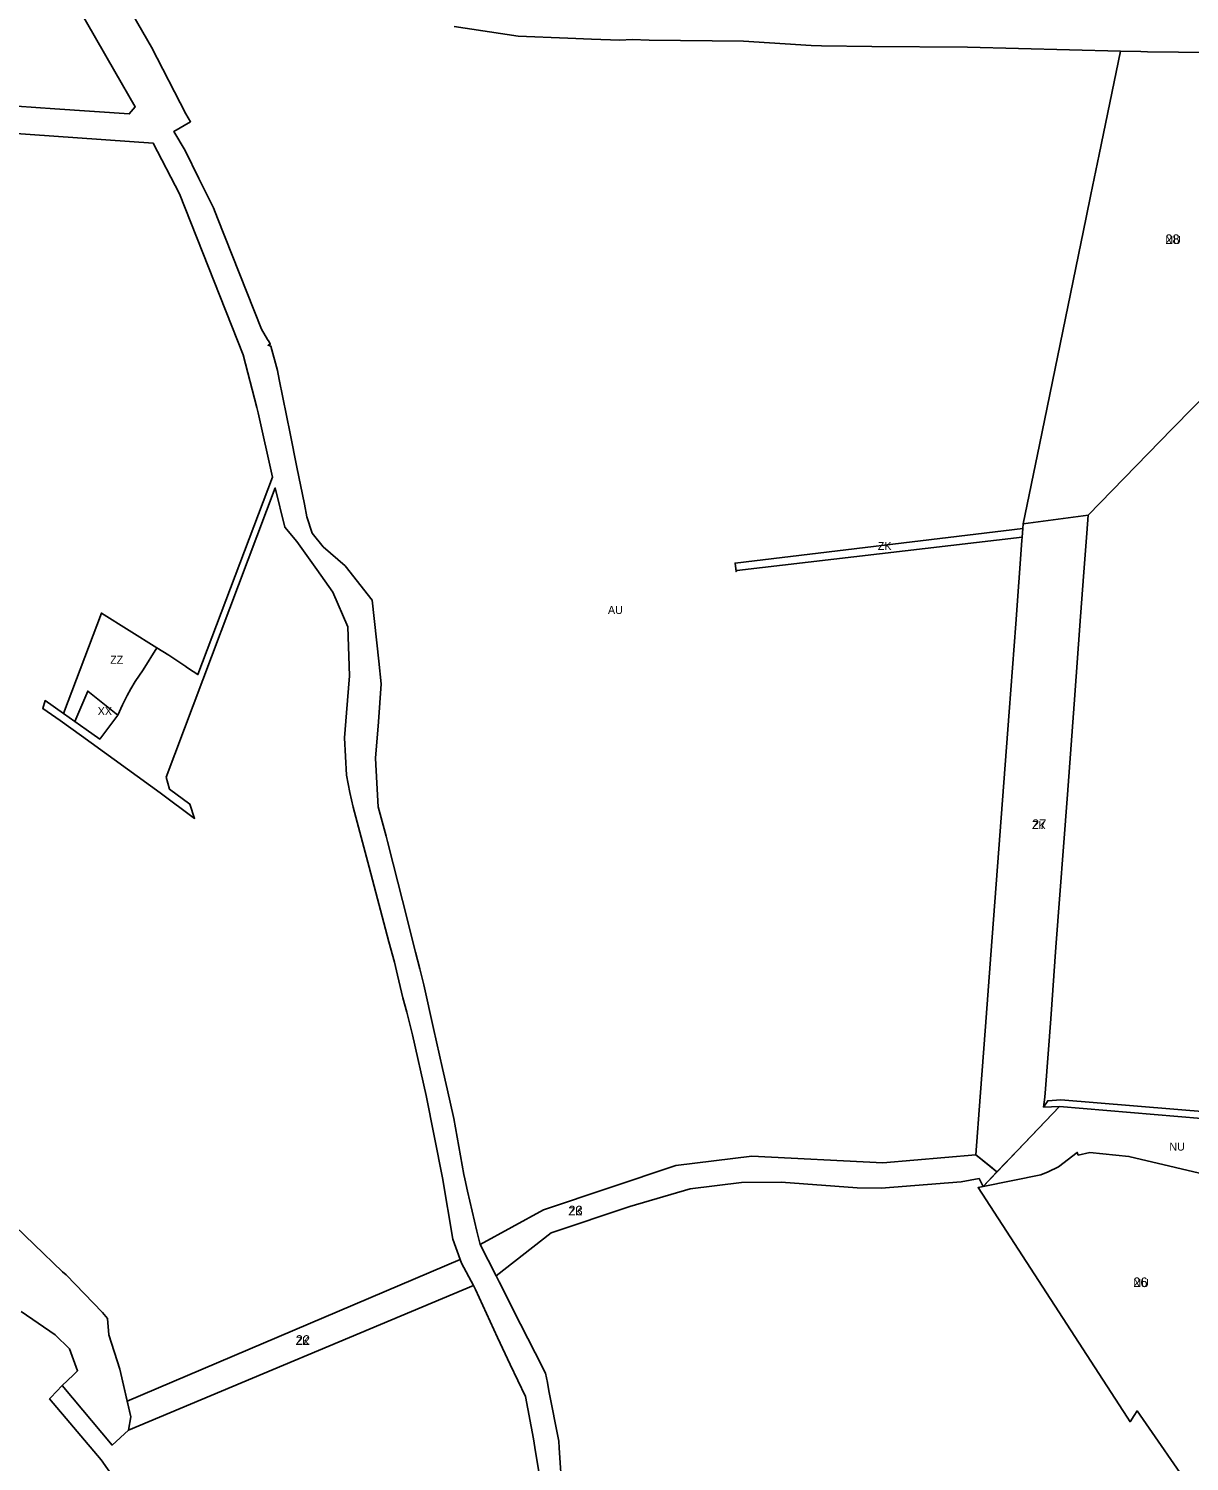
# Model space of a CAD drawing. Extents: x -541351 to -537540, y -1162694 to -1159725.
# Drawn here: x -539459 to -538734, y -1162211 to -1161316 of the extents above; entities that cross this region are included whole.
import ezdxf

# ---------------------------------------------------------------- set-up
doc = ezdxf.new("R2010")
doc.units = 0
for name, color, linetype in [('90550013', 7, 'Continuous'), ('90670013', 7, 'Continuous'), ('90710013', 7, 'Continuous'), ('90710023', 7, 'Continuous'), ('90730013', 7, 'Continuous'), ('90730023', 7, 'Continuous'), ('90750013', 7, 'Continuous'), ('ID_navrh', 7, 'Continuous')]:
    doc.layers.add(name, color=color, linetype=linetype)

msp = doc.modelspace()

# ---------------------------------------------------------------- linework, layer by layer
at = {"layer": '90550013'}
msp.add_lwpolyline([(-539403.27, -1161745.18), (-539414.57, -1161760.24), (-539423.02, -1161754.26), (-539430.1, -1161749.19), (-539422.09, -1161730.19)], close=True, dxfattribs=at)
at = {"layer": '90670013'}
msp.add_lwpolyline([(-539378.9, -1161703.23), (-539387.58, -1161716.88), (-539392.51, -1161724.29), (-539395.12, -1161728.84), (-539397.57, -1161733.03), (-539400.32, -1161738.89), (-539403.27, -1161745.18), (-539422.09, -1161730.19), (-539430.1, -1161749.19), (-539437.27, -1161744.18), (-539413.6, -1161681.54)], close=True, dxfattribs=at)
at = {"layer": '90710013'}
msp.add_lwpolyline([(-539017.23, -1161655.55), (-539017.95, -1161650.26), (-538838.219, -1161628.655), (-538838.622, -1161634.028), (-539016.74, -1161654.92)], close=True, dxfattribs=at)
at = {"layer": '90710023'}
for points in [[(-538838.219, -1161628.655), (-538838.005, -1161625.799), (-538797.48, -1161620.29), (-538798.31, -1161631.51), (-538800.12, -1161655.85), (-538802.17, -1161683.57), (-538806.25, -1161738.46), (-538810.43, -1161794.77), (-538817.52, -1161890.24), (-538820.83, -1161934.92), (-538824.09, -1161978.8), (-538824.47, -1161983.94), (-538825.25, -1161990.14), (-538815.36, -1161989.8), (-538842.019, -1162017.71), (-538854.36, -1162030.631), (-538867.535, -1162019.889), (-538864.817, -1161983.614), (-538861.529, -1161939.738), (-538858.176, -1161894.991), (-538846.804, -1161743.228), (-538842.689, -1161688.306), (-538838.789, -1161636.259), (-538838.622, -1161634.028)], [(-538854.36, -1162030.631), (-538863.08, -1162039.76), (-538865.57, -1162034.76), (-538865.57, -1162034.76), (-538876.72, -1162036.74), (-538926.62, -1162040.85), (-538941.77, -1162040.48), (-538989.17, -1162037.11), (-539013.92, -1162037.13), (-539045.95, -1162041.27), (-539083.65, -1162052.18), (-539132.72, -1162068.62), (-539167.17, -1162095.62), (-539177.1, -1162076.06), (-539137.485, -1162054.397), (-539054.974, -1162026.594), (-539007.532, -1162020.741), (-538925.739, -1162024.857), (-538867.535, -1162019.889), (-538858.418, -1162027.322)], [(-539188.8, -1162087.6), (-539181.321, -1162101.563), (-539396.737, -1162192.032), (-539395.121, -1162183.629), (-539397.38, -1162173.819), (-539189.627, -1162085.25)]]:
    msp.add_lwpolyline(points, close=True, dxfattribs=at)
at = {"layer": '90730013'}
msp.add_lwpolyline([(-538636.08, -1162004.76), (-538644.52, -1162009.98), (-538647.92, -1162012.08), (-538664.06, -1162033.48), (-538673.38, -1162035.73), (-538671.98, -1162042.69), (-538672.267, -1162044.823), (-538672.267, -1162044.823), (-538713.86, -1162034.77), (-538772.02, -1162020.88), (-538796.41, -1162018.51), (-538803.58, -1162020.1), (-538804.26, -1162018.41), (-538816.04, -1162027.52), (-538822.45, -1162030.47), (-538826.9, -1162032.51), (-538863.08, -1162039.76), (-538815.36, -1161989.8), (-538711.96, -1161998.43)], close=True, dxfattribs=at)
msp.add_lwpolyline([(-539473.3, -1162058.96), (-539437.95, -1162093.1), (-539435.62, -1162095.01), (-539412.98, -1162118.53), (-539409.81, -1162122.16), (-539409.81, -1162122.16), (-539408.87, -1162132.42), (-539408.87, -1162132.42), (-539401.987, -1162153.807), (-539395.121, -1162183.629), (-539396.737, -1162192.032), (-539406.94, -1162201.22), (-539438.02, -1162164.06), (-539431.19, -1162157.52), (-539428.42, -1162154.88), (-539433.54, -1162141.24), (-539442.45, -1162132.43), (-539463.62, -1162117.77)], dxfattribs=at)
at = {"layer": '90730023'}
for points in [[(-538838.005, -1161625.799), (-538827.847, -1161576.385), (-538798.665, -1161434.423), (-538795.685, -1161419.928), (-538790.55, -1161394.945), (-538777.276, -1161330.371), (-538764.566, -1161330.69), (-538760.434, -1161330.846), (-538702.278, -1161331.538), (-538660.482, -1161332.245), (-538705.32, -1161525.94), (-538744.9, -1161566.45), (-538797.48, -1161620.29)], [(-538713.86, -1162034.77), (-538672.267, -1162044.823), (-538673.105, -1162051.048), (-538695.05, -1162214.09), (-538712.27, -1162226.46), (-538729.02, -1162231.4), (-538730.919, -1162231.96), (-538766.94, -1162179.94), (-538768.78, -1162182.83), (-538771.26, -1162186.72), (-538773.11, -1162183.87), (-538866.22, -1162040.39), (-538863.08, -1162039.76), (-538826.9, -1162032.51), (-538822.45, -1162030.47), (-538816.04, -1162027.52), (-538804.26, -1162018.41), (-538803.58, -1162020.1), (-538796.41, -1162018.51), (-538772.02, -1162020.88)]]:
    msp.add_lwpolyline(points, close=True, dxfattribs=at)
at = {"layer": '90750013'}
for points in [[(-539468.39, -1161234.85), (-539453.999, -1161259.118), (-539447.73, -1161269.69), (-539434.98, -1161291.19), (-539405.14, -1161343.09), (-539392.4, -1161365.24), (-539396.15, -1161369.7), (-539442.69, -1161366.45), (-539490.23, -1161363.16)], [(-539193.318, -1161315.105), (-539153.268, -1161321.094), (-539122.293, -1161322.252), (-539107.636, -1161322.955), (-539089.891, -1161323.5), (-539082.223, -1161323.25), (-539071.627, -1161323.569), (-539012.669, -1161324.213), (-538970.356, -1161326.967), (-538963.886, -1161327.088), (-538932.513, -1161327.519), (-538872.877, -1161327.968), (-538777.276, -1161330.371), (-538777.276, -1161330.371), (-538790.55, -1161394.945), (-538795.685, -1161419.928), (-538798.665, -1161434.423), (-538827.847, -1161576.385), (-538838.005, -1161625.799), (-538838.219, -1161628.655), (-539017.95, -1161650.26), (-539017.23, -1161655.55), (-539016.74, -1161654.92), (-538838.622, -1161634.028), (-538838.789, -1161636.259), (-538842.689, -1161688.306), (-538846.804, -1161743.228), (-538858.176, -1161894.991), (-538861.529, -1161939.738), (-538864.817, -1161983.614), (-538867.535, -1162019.889), (-538925.739, -1162024.857), (-539007.532, -1162020.741), (-539054.974, -1162026.594), (-539137.485, -1162054.397), (-539177.1, -1162076.06), (-539177.1, -1162076.06), (-539179.07, -1162067.59), (-539184.9, -1162042.56), (-539186.67, -1162034.94), (-539187.18, -1162032.19), (-539193.59, -1161997.34), (-539197.76, -1161978.7), (-539200.6, -1161966.02), (-539206.22, -1161940.94), (-539212.32, -1161913.69), (-539214.84, -1161903.7), (-539217.45, -1161893.33), (-539225.57, -1161861.14), (-539231.34, -1161838.25), (-539234.86, -1161824.29), (-539235.74, -1161820.78), (-539240.72, -1161802.49), (-539241.52, -1161787.71), (-539242.37, -1161772.11), (-539240.64, -1161749.54), (-539238.81, -1161725.75), (-539240.34, -1161711.55), (-539244.42, -1161673.52), (-539261.46, -1161651.91), (-539275.02, -1161640.13), (-539281.97, -1161631.64), (-539285.25, -1161621.38), (-539286.85, -1161613.44), (-539291.53, -1161590.26), (-539295.77, -1161569.23), (-539302.55, -1161535.61), (-539303.69, -1161529.93), (-539307.78, -1161514.67), (-539309.47, -1161514.21), (-539308.09, -1161513.51), (-539308.92, -1161512.11), (-539309.76, -1161510.68), (-539313.61, -1161504.16), (-539341.16, -1161434.73), (-539343.67, -1161428.41), (-539352.75, -1161410.03), (-539361.37, -1161392.57), (-539368.278, -1161380.57), (-539357.878, -1161374.583), (-539360.762, -1161369.573), (-539382.245, -1161327.916), (-539417.292, -1161267.224)], [(-539505.512, -1161379.19), (-539381.181, -1161387.997), (-539381.181, -1161387.997), (-539364.89, -1161419.69), (-539325.02, -1161520.27), (-539316.47, -1161553.16), (-539315.76, -1161556.43), (-539306.78, -1161596.54), (-539353.29, -1161719.96), (-539359.12, -1161716.15), (-539360.62, -1161715.05), (-539360.91, -1161714.86), (-539371.51, -1161707.71), (-539378.9, -1161703.23), (-539413.6, -1161681.54), (-539437.27, -1161744.18), (-539448.59, -1161736.16), (-539450.22, -1161741.11), (-539439.41, -1161748.71), (-539426, -1161758.14), (-539376.97, -1161793.72), (-539355.34, -1161809.82), (-539358.35, -1161800.84), (-539371.01, -1161791.56), (-539373.09, -1161783.93), (-539305.07, -1161603.34), (-539299.04, -1161627.81), (-539291.45, -1161636.72), (-539279.15, -1161654.33), (-539269.09, -1161668.45), (-539259.73, -1161690.18), (-539258.67, -1161720.64), (-539260.49, -1161743.77), (-539261.83, -1161759.51), (-539260.63, -1161782.68), (-539258.35, -1161793.49), (-539256.35, -1161802.83), (-539246.32, -1161840.14), (-539234.16, -1161886.78), (-539230.64, -1161899.55), (-539228.65, -1161907.73), (-539225.42, -1161921.81), (-539222.91, -1161930.72), (-539219.35, -1161944.98), (-539210.77, -1161982.93), (-539200.52, -1162034.32), (-539194.04, -1162072.72), (-539189.627, -1162085.25), (-539189.627, -1162085.25), (-539397.38, -1162173.819), (-539401.987, -1162153.807), (-539408.87, -1162132.42), (-539408.87, -1162132.42), (-539409.81, -1162122.16), (-539409.81, -1162122.16), (-539412.98, -1162118.53), (-539435.62, -1162095.01), (-539437.95, -1162093.1), (-539473.3, -1162058.96)], [(-538650.79, -1161999.07), (-538814.6, -1161985.57), (-538822.66, -1161986.2), (-538825.25, -1161990.14), (-538824.47, -1161983.94), (-538824.09, -1161978.8), (-538820.83, -1161934.92), (-538817.52, -1161890.24), (-538810.43, -1161794.77), (-538806.25, -1161738.46), (-538802.17, -1161683.57), (-538800.12, -1161655.85), (-538798.31, -1161631.51), (-538797.48, -1161620.29), (-538744.9, -1161566.45), (-538705.32, -1161525.94)], [(-539125.86, -1162230.82), (-539127.7, -1162203.08), (-539127.98, -1162198.77), (-539134.14, -1162167.31), (-539135.1, -1162162.18), (-539136.3, -1162156.43), (-539142.82, -1162143.59), (-539151.92, -1162125.67), (-539165.27, -1162099.36), (-539167.17, -1162095.62), (-539132.72, -1162068.62), (-539083.65, -1162052.18), (-539045.95, -1162041.27), (-539013.92, -1162037.13), (-538989.17, -1162037.11), (-538941.77, -1162040.48), (-538926.62, -1162040.85), (-538876.72, -1162036.74), (-538865.57, -1162034.76), (-538863.08, -1162039.76), (-538866.22, -1162040.39), (-538773.11, -1162183.87), (-538771.26, -1162186.72), (-538768.78, -1162182.83), (-538766.94, -1162179.94), (-538730.919, -1162231.96)], [(-539363.42, -1162282.15), (-539413.74, -1162210.51), (-539445.96, -1162172.37), (-539445.09, -1162171.46), (-539441.51, -1162167.71), (-539438.02, -1162164.06), (-539406.94, -1162201.22), (-539396.737, -1162192.032), (-539181.321, -1162101.563), (-539180.01, -1162104.01), (-539166.2, -1162134.06), (-539158.34, -1162150.83), (-539148.72, -1162171), (-539143.8, -1162197.43), (-539142.44, -1162205.39), (-539139.57, -1162222.82)]]:
    msp.add_lwpolyline(points, dxfattribs=at)

# ---------------------------------------------------------------- texts
at = {"layer": '90550013'}
msp.add_text('XX', height=5, rotation=360, dxfattribs=at).set_placement((-539415.86, -1161745.215))
at = {"layer": '90670013'}
msp.add_text('ZZ', height=5, rotation=360, dxfattribs=at).set_placement((-539408.085, -1161713.166))
at = {"layer": '90710013'}
msp.add_text('ZK', height=5, rotation=0, dxfattribs=at).set_placement((-538928.775, -1161642.103))
at = {"layer": '90710023'}
msp.add_text('ZK', height=5, dxfattribs=at).set_placement((-538832.508, -1161816.402))
for rotation, p in [(360, (-539121.957, -1162057.754)), (0, (-539292.236, -1162138.641))]:
    msp.add_text('ZK', height=5, rotation=rotation, dxfattribs=at).set_placement(p)
at = {"layer": '90730013'}
msp.add_text('NU', height=5, rotation=360, dxfattribs=at).set_placement((-538746.752, -1162017.311))
at = {"layer": '90730023'}
for p in [(-538749.243, -1161450.938), (-538769.243, -1162102.55)]:
    msp.add_text('NU', height=5, rotation=0, dxfattribs=at).set_placement(p)
at = {"layer": '90750013'}
msp.add_text('AU', height=5, rotation=0, dxfattribs=at).set_placement((-539097.284, -1161682.062))
at = {"layer": 'ID_navrh'}
for s, rotation, p in [('28', 360, (-538749.243, -1161450.938)), ('27', 0, (-538832.508, -1161816.402)), ('23', 360, (-539121.957, -1162057.754)), ('26', 0, (-538769.243, -1162102.55)), ('22', 360, (-539292.236, -1162138.641))]:
    msp.add_text(s, height=6, rotation=rotation, dxfattribs=at).set_placement(p)

doc.saveas('drawing.dxf')
